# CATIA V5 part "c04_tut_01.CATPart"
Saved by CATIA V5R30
Part number: c04tut01
Material "Copper": density 8900 kg/m3, Young's modulus 1.1e+11 Pa, Poisson ratio 0.33, thermal expansion 1.65e-05 1/K
Bounding box of the stored display mesh (mm): x -99.742 to 99.742, y -99.922 to 99.922, z 0 to 140
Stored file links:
  D:\PROJECTS\CATIA V56R 2020\Resources\c04\c04_tut_01.CATPart
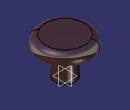
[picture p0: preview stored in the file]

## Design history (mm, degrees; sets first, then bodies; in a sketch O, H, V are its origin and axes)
Body1 (main body), material "Copper"
  Sketch1 on yz-plane, origin (0, 0, 0), H (0, 1, 0), V (0, 0, 1)
    axis line L1 (0, -20) -> (0, 90)
    point P1 (0, -20)
    line L2 (0, 0) -> (0, 140)
    line L3 (0, 140) -> (75, 140)
    arc A1 centre (75, 115) radius 25 from (75, 140) to (66.6667, 91.4298) cw
    arc A2 centre (60, 72.5736) radius 20 from (66.6667, 91.4298) to (40, 72.5736) ccw
    line L4 (40, 72.5736) -> (40, 0)
    point P9 (40, 0)
    line L5 (40, 0) -> (0, 0)
    radius about axis L4 L1 = 40
    radius about axis L1 A1 = 100
    radius A2 = 20
    radius A1 = 25
    distance L5 L3 = 140
    coincidence: P1 V, P9 H, P1 L2
    vertical: L1 V, L2 V
    horizontal: L3 H, L5 H
    tangency: A1 L3, A2 A1, L4 A2
  Shaft1: profile Sketch1, axis Sketch1.L1, angle 360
